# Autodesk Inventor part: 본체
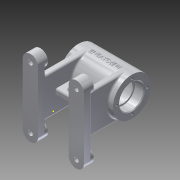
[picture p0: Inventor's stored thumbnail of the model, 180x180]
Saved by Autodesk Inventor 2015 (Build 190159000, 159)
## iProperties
Created: 2015-11
Part Number: 본체
Material: 알루미늄 6061
Document SubType Name: Modeling
Designer: Administrator
Density: 2.7 g/cm^3
Appearance: 알루미늄 - 평지
Author: Administrator
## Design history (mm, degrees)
sketch "스케치8"
  geometry: L1 (40, 40)-(40, -40); L2 (20, 40)-(20, -40); L3 (-20, 40)-(-20, -40); L4 (-40, 40)-(-40, -40); A1 r 10 centre (30, 40) between (40, 40) and (20, 40); A2 r 10 centre (30, -40) between (20, -40) and (40, -40); A3 r 10 centre (-30, 40) between (-20, 40) and (-40, 40); A4 r 10 centre (-30, -40) between (-40, -40) and (-20, -40); 3 further points
  constraints: 8 end point, 8 point on circle, 8 tangent, 4 centre point, 2 parallel, 2 vertical, 1 equal radius, 1 horizontal alignment, 1 vertical alignment
  dimensions: "d54" = 10 radius of A1; "d57" = 0 distance from line of point (40, 0) L1
extrude "돌출3" new body sketch "스케치8" distance "d63" = 10; taper "d64" = 0 deg
sketch "스케치9"
  geometry: L1 (-40, -40)-(-40, 40) reference; L2 (-20, 40)-(-20, -40) reference; L3 (20, -40)-(20, 40) reference; L4 (40, 40)-(40, -40) reference; A1 r 10 centre (-30, 40) between (-20, 40) and (-40, 40) reference; A2 r 10 centre (-30, -40) between (-40, -40) and (-20, -40) reference; A3 r 10 centre (30, -40) between (20, -40) and (40, -40) reference; A4 r 10 centre (30, 40) between (40, 40) and (20, 40) reference; 5 further points
  constraints: 4 coincident, 4 horizontal alignment, 8 other
extrude "돌출4" join sketch "스케치9" distance "d65" = 3; taper "d66" = 0 deg
fillet "모깎기2" dims "d67" = 2
sketch "스케치10"
  geometry: L1 (22, 10)-(38, 10) reference; L2 (40, 8)-(40, 0) reference; L3 (40, 0)-(20, 0) reference; L4 (20, 0)-(20, 8) reference; L5 (-38, 10)-(-22, 10) reference; L6 (-20, 8)-(-20, 0) reference; L7 (-20, 0)-(-40, 0) reference; L8 (-40, 0)-(-40, 8) reference; L9 (0, 0)-(0, 68); L10 (35, 68)-(-35, 68); L11 (-35, 68)-(-35, 93); L12 (-35, 93)-(35, 93); L13 (35, 93)-(35, 68); A1 r 2 centre (22, 8) between (22, 10) and (20, 8) reference; A2 r 2 centre (38, 8) between (40, 8) and (38, 10) reference; A3 r 2 centre (-38, 8) between (-38, 10) and (-40, 8) reference; A4 r 2 centre (-22, 8) between (-20, 8) and (-22, 10) reference
  constraints: 10 end point, 2 perpendicular, 2 vertical
  dimensions: "d70" = 68 distance of L9.start L9.end; "d71" = 35 distance of L9.end L10.start; "d72" = 70 distance of L10.start L10.end; "d73" = 25 distance of L10.end L11.end
revolve "회전1" sketch "스케치10" stored, may be unused: angle "d74" = 90 deg
sketch "스케치11"
  geometry: L1 (-31.34, -58)-(31.34, -58) reference; L2 (31.34, -58)-(31.34, -55) reference; L3 (31.34, -55)-(48.66, -55) reference; L4 (48.66, -55)-(48.66, -68) reference; L5 (48.66, -68)-(-48.66, -68) reference; L6 (-48.66, -68)-(-48.66, -55) reference; L7 (-48.66, -55)-(-31.34, -55) reference; L8 (-31.34, -55)-(-31.34, -58) reference; C1 r 25 at (0, 0) reference; A1 r 20 centre (0, 0) between (-20, 0) and (0, 20); 3 further points
  constraints: 4 point on circle, 1 centre point, 1 coincident
  dimensions: "d75" = 40 diameter of A1
hole "구멍6" sketch "스케치11" at (-20, 0), (0, 20), (20, 0), (0, -20) diameter "d76" = 3.242; stored, may be unused: countersink angle "d80" = 90 deg, drill point angle "d82" = 118 deg; dims "d77" = 8, "d78" = 4, "d79" = 2, "d81" = 10
sketch "스케치12"
  geometry: L1 (-31.34, -58)-(31.34, -58) reference; L2 (31.34, -58)-(31.34, -55) reference; L3 (31.34, -55)-(48.66, -55) reference; L4 (48.66, -55)-(48.66, -68) reference; L5 (48.66, -68)-(-48.66, -68) reference; L6 (-48.66, -68)-(-48.66, -55) reference; L7 (-48.66, -55)-(-31.34, -55) reference; L8 (-31.34, -55)-(-31.34, -58) reference; C1 r 1.621 at (20, 0) reference; C2 r 1.621 at (-20, 0) reference; C3 r 1.621 at (0, 20) reference; C4 r 1.621 at (0, -20) reference; C5 r 25 at (0, 0) reference; 1 further point
hole "구멍7" sketch "스케치12" at (0, 0) diameter "d83" = 32; stored, may be unused: countersink angle "d87" = 90 deg, drill point angle "d89" = 0 deg; dims "d84" = 8, "d85" = 4, "d86" = 2, "d88" = 12
sketch "스케치13"
  geometry: L1 (-32.859, -58)-(32.859, -58) reference; L2 (32.859, -58)-(32.859, -55) reference; L3 (32.859, -55)-(47.141, -55) reference; L4 (47.141, -55)-(47.141, -68) reference; L5 (47.141, -68)-(-47.141, -68) reference; L6 (-47.141, -68)-(-47.141, -55) reference; L7 (-47.141, -55)-(-32.859, -55) reference; L8 (-32.859, -55)-(-32.859, -58) reference; C1 r 16 at (0, 0) reference; C2 r 25 at (0, 0) reference; 1 further point
hole "구멍8" sketch "스케치13" at (0, 0) diameter "d90" = 28; stored, may be unused: countersink angle "d94" = 90 deg, drill point angle "d96" = 0 deg; dims "d91" = 8, "d92" = 4, "d93" = 2, "d95" = 2
sketch "스케치14"
  geometry: L1 (-44.359, -55)-(-35.641, -55) reference; L2 (-35.641, -55)-(-35.641, -58.268) reference; L3 (-35.641, -58.268)-(35.641, -58.268) reference; L4 (35.641, -58.268)-(35.641, -55) reference; L5 (35.641, -55)-(44.359, -55) reference; L6 (44.359, -55)-(44.359, -68) reference; L7 (44.359, -68)-(-44.359, -68) reference; L8 (-44.359, -68)-(-44.359, -55) reference; C1 r 14 at (0, 0) reference; C2 r 25 at (0, 0) reference; 1 further point
hole "구멍9" sketch "스케치14" at (0, 0) diameter "d97" = 42; stored, may be unused: countersink angle "d101" = 90 deg, drill point angle "d103" = 0 deg; dims "d98" = 8, "d99" = 4, "d100" = 2, "d102" = 42
chamfer "모따기3" distance "d104" = 1; stored, may be unused: second distance "d105" = 2, angle "d106" = 45 deg
chamfer "모따기4" distance "d107" = 1; stored, may be unused: second distance "d108" = 2, angle "d109" = 45 deg
fillet "모깎기3" dims "d110" = 3
node "작업 평면5"
  node "작업 평면4"
sketch "스케치15"
  geometry: L1 (35, -25)-(-35, -25) reference; L2 (35, 25)-(35, -25) reference; L3 (35, 25)-(-35, 25) reference; L4 (-35, 25)-(-35, -25) reference; C1 r 5 at (0, 0); 1 further point
  constraints: 1 centre point, 1 coincident
  dimensions: "d112" = 10 diameter of C1
extrude "돌출5" join sketch "스케치15" stored distance "d113" = 70; taper "d114" = 0 deg
fillet "모깎기4" dims "d115" = 2
sketch "스케치16"
  geometry: C1 r 5 at (0, 0) reference; 1 further point
hole "구멍10" sketch "스케치16" at (0, 0) diameter "d116" = 5.188; stored, may be unused: countersink angle "d120" = 90 deg, drill point angle "d122" = 0 deg; dims "d117" = 15, "d118" = 4, "d119" = 2, "d121" = 15
sketch "스케치17"
  geometry: L1 (0, 8)-(80, 8) reference; L2 (80, 0)-(80, 8) reference; L3 (80, 0)-(0, 0) reference; L4 (0, 0)-(0, 8) reference; L5 (0, 8)-(0, 13) reference; L6 (80, 8)-(80, 13) reference; L7 (40, 0)-(15, 0); L8 (80, 0)-(0, 0) reference; L9 (15, 0)-(15, 67); L10 (15, 0)-(65, 0); L11 (65, 0)-(65, 67); L12 (65, 67)-(53.394, 48.192); L13 (53.394, 48.192)-(40, 44.602); L14 (40, 44.602)-(25.54, 50.049); L15 (25.54, 50.049)-(15, 67); C1 r 25 at (40, 68) reference; C2 r 20.236 at (40, 68) reference
  constraints: 16 end point, 2 point on line, 1 perpendicular
  dimensions: "d126" = 50 distance of L7.end L10.end; "d127" = 90 deg angle of L11 L10
extrude "돌출6" join sketch "스케치17" distance "d128" = 8; taper "d129" = 0 deg
fillet "모깎기6" dims "d131" = 2
sketch "스케치18"
  geometry: L1 (8, -65)-(4, -65) reference; L2 (2, -63)-(2, -17) reference; L3 (4, -15)-(8, -15) reference; L4 (10, -17)-(10, -63) reference; L5 (58, -17)-(58, -63) reference; L6 (56, -65)-(52, -65) reference; L7 (50, -63)-(50, -17) reference; L8 (52, -15)-(56, -15) reference; C1 r 10 at (0, 0) reference; C2 r 10 at (0, -80) reference; C3 r 10 at (60, -80) reference; C4 r 10 at (60, 0) reference; A1 r 2 centre (8, -63) between (8, -65) and (10, -63) reference; A2 r 2 centre (4, -63) between (2, -63) and (4, -65) reference; A3 r 2 centre (4, -17) between (4, -15) and (2, -17) reference; A4 r 2 centre (8, -17) between (10, -17) and (8, -15) reference; A5 r 2 centre (56, -17) between (58, -17) and (56, -15) reference; A6 r 2 centre (56, -63) between (56, -65) and (58, -63) reference; A7 r 2 centre (52, -63) between (50, -63) and (52, -65) reference; A8 r 2 centre (52, -17) between (52, -15) and (50, -17) reference; 1 further point
hole "구멍11" sketch "스케치18" at (60, 0), (0, 0) diameter "d132" = 12; stored, may be unused: countersink angle "d136" = 90 deg, drill point angle "d138" = 0 deg; dims "d133" = 3, "d134" = 4, "d135" = 2, "d137" = 4
sketch "스케치19"
  geometry: L1 (8, 15)-(4, 15) reference; L2 (2, 17)-(2, 63) reference; L3 (4, 65)-(8, 65) reference; L4 (10, 63)-(10, 17) reference; L5 (58, 63)-(58, 17) reference; L6 (56, 15)-(52, 15) reference; L7 (50, 17)-(50, 63) reference; L8 (52, 65)-(56, 65) reference; C1 r 6 at (60, 80) reference; C2 r 6 at (0, 80) reference; C3 r 10 at (0, 80) reference; C4 r 10 at (0, 0) reference; C5 r 10 at (60, 0) reference; C6 r 10 at (60, 80) reference; A1 r 2 centre (8, 17) between (8, 15) and (10, 17) reference; A2 r 2 centre (4, 17) between (2, 17) and (4, 15) reference; A3 r 2 centre (4, 63) between (4, 65) and (2, 63) reference; A4 r 2 centre (8, 63) between (10, 63) and (8, 65) reference; A5 r 2 centre (56, 63) between (58, 63) and (56, 65) reference; A6 r 2 centre (56, 17) between (56, 15) and (58, 17) reference; A7 r 2 centre (52, 17) between (50, 17) and (52, 15) reference; A8 r 2 centre (52, 63) between (52, 65) and (50, 63) reference; 1 further point
hole "구멍12" sketch "스케치19" at (0, 0), (60, 0) diameter "d139" = 12; stored, may be unused: countersink angle "d143" = 90 deg, drill point angle "d145" = 0 deg; dims "d140" = 3, "d141" = 4, "d142" = 2, "d144" = 4
node "작업 평면11"
sketch "스케치20"
  geometry: L1 (-9.732, -77.701)-(-9.732, -2.299) reference; L2 (9.732, -2.299)-(9.732, -16) reference; L3 (10, -17)-(10, -63) reference; L4 (9.732, -64)-(9.732, -77.701) reference; L5 (69.732, -2.299)-(69.732, -77.701) reference; L6 (50.268, -77.701)-(50.268, -64) reference; L7 (50, -63)-(50, -17) reference; L8 (50.268, -16)-(50.268, -2.299) reference; C1 r 6 at (0, -80) reference; C2 r 6 at (60, -80) reference; C3 r 6 at (60, 0) reference; C4 r 6 at (0, 0) reference; A1 r 10 centre (0, 0) between (9.732, -2.299) and (-9.732, -2.299) reference; A2 r 2 centre (8, -17) between (10, -17) and (9.732, -16) reference; A3 r 2 centre (8, -63) between (9.732, -64) and (10, -63) reference; A4 r 10 centre (0, -80) between (-9.732, -77.701) and (9.732, -77.701) reference; A5 r 10 centre (60, -80) between (50.268, -77.701) and (69.732, -77.701) reference; A6 r 2 centre (52, -63) between (50, -63) and (50.268, -64) reference; A7 r 2 centre (52, -17) between (50.268, -16) and (50, -17) reference; A8 r 10 centre (60, 0) between (69.732, -2.299) and (50.268, -2.299) reference; 5 further points
hole "구멍13" sketch "스케치20" at (0, 0), (60, 0), (60, -80), (0, -80) diameter "d147" = 6; stored, may be unused: countersink angle "d151" = 90 deg, drill point angle "d153" = 0 deg; dims "d148" = 3, "d149" = 4, "d150" = 2, "d152" = 15
fillet "모깎기8" dims "d174" = 2
sketch "스케치23"
  geometry: L1 (-24.026, 88)-(-25, 89.621) reference; L2 (-25, 89.621)-(-35, 89.621) reference; L3 (-35, 89.621)-(-35, 93) reference; L4 (-35, 93)-(-7, 93) reference; L5 (-5, 95)-(-5, 96) reference; L6 (-5, 96)-(-2.594, 96) reference; L7 (-2.594, 96)-(-2.594, 89) reference; L8 (2.594, 89)-(2.594, 96) reference; L9 (2.594, 96)-(5, 96) reference; L10 (5, 96)-(5, 95) reference; L11 (7, 93)-(35, 93) reference; L12 (35, 93)-(35, 89.621) reference; L13 (35, 89.621)-(25, 89.621) reference; L14 (25, 89.621)-(24.026, 88) reference; L15 (24.026, 88)-(25, 86.379) reference; L16 (25, 86.379)-(35, 86.379) reference; L17 (35, 86.379)-(35, 85) reference; L18 (35, 85)-(34, 84) reference; L19 (34, 84)-(23, 84) reference; L20 (23, 84)-(23, 82) reference; L21 (23, 82)-(21, 82) reference; L22 (21, 82)-(21, 86) reference; L23 (18, 89)-(2.594, 89) reference; L24 (-21, 86)-(-21, 82) reference; L25 (-21, 82)-(-23, 82) reference; L26 (-23, 82)-(-23, 84) reference; L27 (-23, 84)-(-34, 84) reference; L28 (-34, 84)-(-35, 85) reference; L29 (-35, 85)-(-35, 86.379) reference; L30 (-35, 86.379)-(-25, 86.379) reference; L31 (-25, 86.379)-(-24.026, 88) reference; L32 (-24.026, 48)-(-25, 49.621) reference; L33 (-25, 49.621)-(-35, 49.621) reference; L34 (-35, 49.621)-(-35, 51) reference; L35 (-35, 51)-(-34, 52) reference; L36 (-34, 52)-(-23, 52) reference; L37 (-23, 52)-(-23, 54) reference; L38 (-23, 54)-(-21, 54) reference; L39 (-21, 54)-(-21, 50) reference; L40 (-18, 47)-(18, 47) reference; L41 (21, 50)-(21, 54) reference; L42 (21, 54)-(23, 54) reference; L43 (23, 54)-(23, 52) reference; L44 (23, 52)-(34, 52) reference; L45 (34, 52)-(35, 51) reference; L46 (35, 51)-(35, 49.621) reference; L47 (35, 49.621)-(25, 49.621) reference; L48 (25, 49.621)-(24.026, 48) reference; L49 (24.026, 48)-(25, 46.379) reference; L50 (25, 46.379)-(35, 46.379) reference; L51 (35, 46.379)-(35, 43) reference; L52 (35, 43)-(28, 43) reference; L53 (28, 43)-(28, 10) reference; L54 (28, 10)-(38, 10) reference; L55 (40, 8)-(40, 0) reference; L56 (40, 0)-(20, 0) reference; L57 (20, 0)-(20, 41) reference; L58 (18, 43)-(-18, 43) reference; L59 (-20, 41)-(-20, 0) reference; L60 (-20, 0)-(-40, 0) reference; L61 (-40, 0)-(-40, 8) reference; L62 (-38, 10)-(-28, 10) reference; L63 (-28, 10)-(-28, 43) reference; L64 (-28, 43)-(-35, 43) reference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; A1 r 3 centre (18, 86) between (21, 86) and (18, 89) reference; A2 r 3 centre (-18, 86) between (-18, 89) and (-21, 86) reference; A3 r 3 centre (-18, 50) between (-21, 50) and (-18, 47) reference; A4 r 3 centre (18, 50) between (18, 47) and (21, 50) reference; A5 r 2 centre (38, 8) between (40, 8) and (38, 10) reference; A6 r 2 centre (18, 41) between (20, 41) and (18, 43) reference; A7 r 2 centre (-18, 41) between (-18, 43) and (-20, 41) reference; A8 r 2 centre (-38, 8) between (-38, 10) and (-40, 8) reference; 1 further point
  constraints: 10 end point, 2 collinear, 2 perpendicular, 2 point on line, 1 horizontal, 1 parallel, 2 other
  dimensions: "d175" = 20 distance of L69.start L69.end; "d176" = 90 deg angle of L69 L70 (derived)
extrude "돌출8" join sketch "스케치23" stored distance "d177" = 8; taper "d178" = 0 deg
fillet "모깎기9" dims "d185" = 2
fillet "모깎기10" dims "d186" = 2
node "작업 평면6"
node "작업 평면7"
sketch "스케치25"
  geometry: L1 (-38, 10)-(-22, 10) reference; L2 (-20, 8)-(-20, 0) reference; L3 (-20, 0)-(-40, 0) reference; L4 (-40, 0)-(-40, 8) reference; L5 (22, 10)-(38, 10) reference; L6 (40, 8)-(40, 0) reference; L7 (40, 0)-(20, 0) reference; L8 (20, 0)-(20, 8) reference; L9 (-35, 43)-(-35, 93) reference; L10 (35, 43)-(35, 93) reference; L11 (-35, 93)-(35, 93) reference; A1 r 2 centre (-38, 8) between (-38, 10) and (-40, 8) reference; A2 r 2 centre (-22, 8) between (-20, 8) and (-22, 10) reference; A3 r 2 centre (38, 8) between (40, 8) and (38, 10) reference; A4 r 2 centre (22, 8) between (22, 10) and (20, 8) reference; 3 further points
  constraints: 1 coincident, 1 other
feature "엠보싱1" sketch "스케치25" dims "d190" = 0.5, "d191" = 0
node "작업축1"
node "작업 평면10"
  node "작업 평면9"
sketch "스케치28"
  geometry: 1 further point
sketch "스케치29"
  geometry: L1 (35, 51.477)-(35, 43.322) reference; L2 (35, 43.322)-(28, 43.322) reference; L3 (28, 43.322)-(28, 10) reference; L4 (28, 10)-(38, 10) reference; L5 (40, 8)-(40, 0) reference; L6 (40, 0)-(20, 0) reference; L7 (20, 0)-(20, 25) reference; L8 (-20, 25)-(20, 25) reference; L9 (-20, 41)-(-20, 25) reference; L10 (20, 41)-(-20, 41) reference; L11 (20, 41)-(20, 41.298) reference; L12 (18, 43.322)-(-18, 43.322) reference; L13 (-20, 41.298)-(-20, 41) reference; L14 (23, 52.508)-(34, 52.508) reference; L15 (23, 54.584)-(23, 52.508) reference; L16 (21, 54.584)-(23, 54.584) reference; L17 (21, 50.45)-(21, 54.584) reference; L18 (-18, 47.384)-(18, 47.384) reference; L19 (-21, 54.584)-(-21, 50.45) reference; L20 (-23, 54.584)-(-21, 54.584) reference; L21 (-23, 52.508)-(-23, 54.584) reference; L22 (-34, 52.508)-(-23, 52.508) reference; L23 (-35, 43.322)-(-35, 51.477) reference; L24 (-28, 43.322)-(-35, 43.322) reference; L25 (-28, 10)-(-28, 43.322) reference; L26 (-38, 10)-(-28, 10) reference; L27 (-40, 0)-(-40, 8) reference; L28 (-20, 0)-(-40, 0) reference; L29 (-20, 25)-(-20, 0) reference; L30 (20, 25)-(20, 41) reference; L31 (34, 83.492)-(23, 83.492) reference; L32 (23, 83.492)-(23, 81.416) reference; L33 (23, 81.416)-(21, 81.416) reference; L34 (21, 81.416)-(21, 85.55) reference; L35 (18, 88.616)-(-18, 88.616) reference; L36 (-21, 85.55)-(-21, 81.416) reference; L37 (-21, 81.416)-(-23, 81.416) reference; L38 (-23, 81.416)-(-23, 83.492) reference; L39 (-23, 83.492)-(-34, 83.492) reference; L40 (-35, 84.523)-(-35, 92.678) reference; L41 (-35, 92.678)-(-5.508, 92.678) reference; L42 (-3, 94.413)-(-3, 96) reference; L43 (-3, 96)-(3, 96) reference; L44 (3, 96)-(3, 94.413) reference; L45 (5.508, 92.678)-(35, 92.678) reference; L46 (35, 92.678)-(35, 84.523) reference; L47 (-20, 0)-(-20, 33); L48 (-20, 8)-(-20, 53.858) reference; L49 (-8, 36.5)-(8, 36.5); L50 (-8, 29.5)-(8, 29.5); A1 r 2 centre (38, 8) between (40, 8) and (38, 10) reference; A2 r 2 centre (-38, 8) between (-38, 10) and (-40, 8) reference; A3 r 3.5 centre (-8, 33) between (-8, 36.5) and (-8, 29.5); A4 r 3.5 centre (8, 33) between (8, 29.5) and (8, 36.5); 1 further point
  constraints: 6 end point, 4 point on circle, 2 centre point, 1 point on line, 1 tangent, 12 other
  dimensions: "d206" = 33 distance of L28.start L47.end
extrude "돌출11" cut sketch "스케치29" distance "d211" = 8; taper "d212" = 0 deg
fillet "모깎기12" dims "d213" = 2
fillet "모깎기13" dims "d214" = 2
fillet "모깎기14" dims "d215" = 2
fillet "모깎기15" dims "d216" = 2
fillet "모깎기16" dims "d220" = 0.3
chamfer "모따기8" distance "d221" = 1; stored, may be unused: second distance "d222" = 2, angle "d223" = 45 deg
chamfer "모따기9" distance "d224" = 1; stored, may be unused: second distance "d225" = 2, angle "d226" = 45 deg
chamfer "모따기10" distance "d227" = 1; stored, may be unused: second distance "d228" = 2, angle "d229" = 45 deg
chamfer "모따기11" distance "d230" = 1; stored, may be unused: second distance "d231" = 2, angle "d232" = 45 deg
fillet "모깎기17" dims "d233" = 0.3
node "솔리드2"
mirror "대칭4"
mirror "대칭5"
mirror "대칭6"
mirror "대칭7"
node "작업 평면8"
node "절단 모서리 투영2"
node "절단 모서리 투영3"
node "절단 모서리 투영4"
node "절단 모서리 투영5"
node "절단 모서리 투영6"
node "절단 모서리 투영7"
node "절단 모서리 투영8"
node "절단 모서리 투영9"
node "절단 모서리 투영10"
node "절단 모서리 투영11"
node "절단 모서리 투영12"
node "절단 모서리 투영15"
node "절단 모서리 투영17"
node "절단 모서리 투영20"
other parameters: "d111" = 3, "d165" = 11.5, "d172" = 3.5, "d173" = 3.5, "d187" = 25.5, "d192" = 30 deg, "d193" = -60 deg, "d194" = -28
